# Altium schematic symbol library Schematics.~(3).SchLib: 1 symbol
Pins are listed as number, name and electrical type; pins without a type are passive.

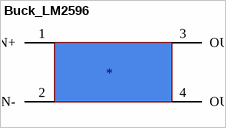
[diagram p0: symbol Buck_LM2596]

## Buck_LM2596
designator ?
footprint Model Name (Footprint not found)
footprint Buck_LM2596
pins: 1 IN+ (power), 2 IN- (power), 3 OUT+ (power), 4 OUT- (power)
